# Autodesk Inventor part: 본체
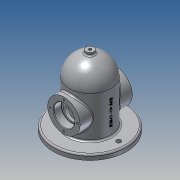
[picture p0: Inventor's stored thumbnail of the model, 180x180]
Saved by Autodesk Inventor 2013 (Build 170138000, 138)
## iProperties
Created: 2019-11
Part Number: 본체
Material: 알루미늄 6061
Document SubType Name: Modeling
Designer: Administrator
Density: 2.71 g/cm^3
Mass: 1110.22 g
Surface Area: 883.263 cm^2
Volume: 409.674 cm^3
Author: Administrator
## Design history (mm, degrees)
sketch "스케치1"
  geometry: C1 r 40 at (0, 0); 1 further point
  constraints: 1 centre point, 1 coincident
  dimensions: "d0" = 80 diameter of C1
extrude "돌출1" new body sketch "스케치1" distance "d1" = 90; taper "d2" = 0 deg
sketch "스케치2"
  geometry: L1 (-40, 0)-(40, 0); A1 r 40 centre (0, 0) between (-40, 0) and (40, 0) reference; A2 r 40 centre (0, 0) between (40, 0) and (-40, 0); 1 further point
  constraints: 4 point on circle, 2 coincident, 2 end point, 1 centre point, 1 midpoint
  dimensions: "d3" = 80 distance of L1.start L1.end
revolve "회전1" sketch "스케치2" stored, may be unused: angle "d5" = 90 deg
feature "쉘1" dims "d6" = 10
sketch "스케치3"
  geometry: C1 r 40 at (0, 0) reference; C2 r 70 at (0, 0)
  constraints: 1 centre point, 1 coincident
  dimensions: "d7" = 140 diameter of C2
extrude "돌출2" join sketch "스케치3" distance "d8" = 10; taper "d9" = 0 deg
node "작업 평면1"
sketch "스케치4"
  geometry: L1 (70, 0)-(-70, 0) reference; C1 r 31 at (0, 50); 1 further point
  constraints: 1 centre point, 1 vertical alignment
  dimensions: "d11" = 62 diameter of C1; "d12" = 50 distance from line of L1 C1.centre
extrude "돌출3" join sketch "스케치4" stored distance "d13" = 10; taper "d14" = 0 deg
sketch "스케치5"
  geometry: C1 r 31 at (0, 0) reference; C2 r 16.5 at (0, 0); 1 further point
  constraints: 1 centre point, 1 coincident
  dimensions: "d15" = 33 diameter of C2
extrude "돌출4" cut sketch "스케치5" stored distance "d16" = 10; taper "d17" = 0 deg
sketch "스케치6"
  geometry: C1 r 16.5 at (0, 0) reference; C2 r 31 at (0, 0) reference; C3 r 20 at (0, 0); 1 further point
  constraints: 1 centre point, 1 coincident
  dimensions: "d18" = 40 diameter of C3
extrude "돌출5" cut sketch "스케치6" distance "d19" = 15; taper "d20" = 0 deg
node "작업 평면2"
sketch "스케치7"
  geometry: C1 r 7.5 at (0, 0); 1 further point
  constraints: 1 centre point, 1 coincident
  dimensions: "d22" = 15 diameter of C1
extrude "돌출6" join sketch "스케치7" stored distance "d23" = 15; taper "d24" = 0 deg
sketch "스케치8"
  geometry: 1 further point
hole "구멍1" sketch "스케치8" at (0, 0) diameter "d25" = 5.188; stored, may be unused: countersink angle "d29" = 90 deg, drill point angle "d31" = 118 deg; dims "d26" = 6, "d27" = 4, "d28" = 2, "d30" = 57
sketch "스케치9" dims "d32" = 52
  geometry: C1 r 31 at (0, 0) reference; 3 further points
  constraints: 2 vertical alignment, 1 coincident, 2 other
hole "구멍2" sketch "스케치9" at (0, 26) diameter "d33" = 3.242; stored, may be unused: countersink angle "d37" = 90 deg, drill point angle "d39" = 118 deg; dims "d34" = 8, "d35" = 4, "d36" = 2, "d38" = 10
sketch "스케치10" dims "d43" = 110
  geometry: C1 r 40 at (0, 0) reference; C2 r 70 at (0, 0) reference; C3 r 4.5 at (0, -55); 1 further point
  constraints: 2 vertical alignment, 1 centre point, 3 other
  dimensions: "d44" = 9 diameter of C3
extrude "돌출7" cut sketch "스케치10" stored distance "d45" = 15; taper "d46" = 0 deg
node "작업 평면4"
  node "작업 평면3"
sketch "스케치11"
  geometry: L1 (70, 0)-(-70, 0) reference; 3 further points
  constraints: 1 midpoint, 1 vertical alignment, 1 other
  dimensions: "d48" = 50 distance from line of L1 point (0, 50)
feature "엠보싱1" sketch "스케치11" dims "d49" = 0.5, "d50" = 0
fillet "모깎기1" dims "d51" = 0.3
chamfer "모따기1" distance "d52" = 1; stored, may be unused: second distance "d53" = 2, angle "d54" = 45 deg
fillet "모깎기2" dims "d55" = 3
node "솔리드1"
mirror "대칭1"
pattern_circular "원형 패턴1" dims angle "d41" = 360 deg
mirror "대칭2"
mirror "대칭3"
node "절단 모서리 투영1"
other parameters: "d21" = -135, "d47" = 21
